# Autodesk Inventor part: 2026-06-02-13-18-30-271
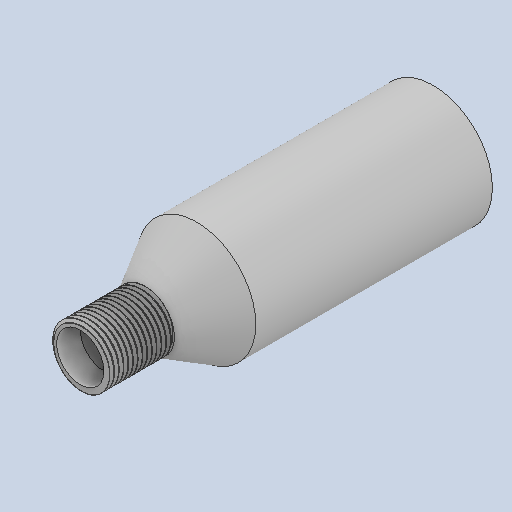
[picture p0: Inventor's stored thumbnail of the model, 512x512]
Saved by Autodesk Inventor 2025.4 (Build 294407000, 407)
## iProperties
Created: 2026-06
Part Number: 2026-06-02-13-18-30-271
Material: Generic
Document SubType Name: Modeling
Designer: AdminForWorker
Density: 1 g/cm^3
Appearance: Default
Title: BOTTLE v1
Author: AdminForWorker
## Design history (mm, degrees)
feature "Body1"
body "Solid1"
